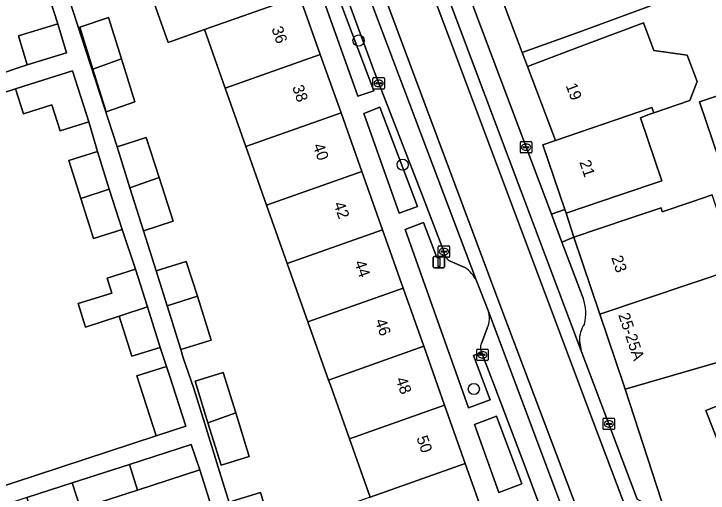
# Model space of a CAD drawing. Extents: x 159371 to 159986, y 382987 to 383597.
# Drawn here: x 159680.8 to 159741.4, y 383240.6 to 383282.5 of the extents above; entities that cross this region are included whole.
import ezdxf

# ---------------------------------------------------------------- set-up
doc = ezdxf.new("R2010")
doc.units = 0
for name, color, linetype in [('IMGEO_Boom', 7, 'Continuous'), ('IMGEO_Erf', 7, 'Continuous'), ('IMGEO_Groenvoorziening', 7, 'Continuous'), ('IMGEO_Kolk', 7, 'Continuous'), ('IMGEO_Lichtmast', 7, 'Continuous'), ('IMGEO_Pand', 7, 'Continuous'), ('IMGEO_Pand_nummerreeks', 7, 'Continuous'), ('IMGEO_Parkeervlak_gesloten', 7, 'Continuous'), ('IMGEO_Parkeervlak_open', 7, 'Continuous'), ('IMGEO_Rijbaan_lokaal_gesloten', 7, 'Continuous'), ('IMGEO_Voetpad_open', 7, 'Continuous')]:
    doc.layers.add(name, color=color, linetype=linetype)

msp = doc.modelspace()

# ---------------------------------------------------------------- linework, layer by layer
at = {"layer": 'IMGEO_Boom'}
for centre in [(159710.901, 383280.138), (159714.755, 383269.277), (159720.969, 383249.658)]:
    msp.add_circle(centre, 0.489, dxfattribs=at)
at = {"layer": 'IMGEO_Erf'}
for points in [[(159682.116, 383294.534), (159689.815, 383270.843), (159692.34, 383271.658), (159693.467, 383268.168), (159694.705, 383264.336), (159692.11, 383263.497), (159693.225, 383260.012), (159695.84, 383260.823), (159696.826, 383257.772), (159698.015, 383253.94), (159695.365, 383253.117), (159695.59, 383252.391), (159696.512, 383249.693), (159697.469, 383246.61), (159698.877, 383242.072), (159702.568, 383230.227)], [(159711.915, 383240.202), (159710.1, 383245.317), (159708.44, 383249.998), (159708.282, 383250.447), (159706.477, 383255.548), (159704.676, 383260.641), (159702.869, 383265.75), (159701.061, 383270.861), (159699.251, 383275.978), (159697.439, 383281.1), (159694.28, 383279.979), (159692.475, 383285.082)], [(159736.412, 383283.168), (159729.903, 383280.793), (159725.198, 383279.1), (159725.656, 383277.87), (159730.333, 383279.64), (159735.782, 383281.701), (159736.698, 383279.28), (159739.618, 383278.871), (159740.492, 383276.551), (159739.844, 383274.897), (159736.695, 383273.822), (159736.17, 383273.643), (159735.541, 383273.369), (159737.394, 383267.859), (159733.76, 383266.636), (159729.021, 383265.042), (159729.705, 383262.938), (159734.445, 383264.533), (159737.321, 383265.5), (159737.433, 383265.168), (159740.025, 383266.04), (159741.795, 383266.635)], [(159678.66, 383240.777), (159693.217, 383245.576), (159691.785, 383250.004), (159691.527, 383250.801), (159694.128, 383251.623), (159693.572, 383253.305), (159691.084, 383252.521), (159689.977, 383256.031), (159687.052, 383255.084), (159686.408, 383257.126), (159689.34, 383258.051), (159688.929, 383259.353), (159691.417, 383260.138), (159690.241, 383263.602), (159687.753, 383262.818), (159686.645, 383266.331), (159685.598, 383269.65), (159688.086, 383270.435), (159687.327, 383273.043), (159684.833, 383272.244), (159684.108, 383274.508), (159681.643, 383273.719), (159680.943, 383275.903), (159668.593, 383271.927)], [(159752.884, 383255.064), (159734.178, 383249.639), (159737.741, 383238.716)]]:
    msp.add_lwpolyline(points, dxfattribs=at)
for points in [[(159684.618, 383281.589), (159682.85, 383287.113), (159677.624, 383285.316), (159676.828, 383287.631), (159671.727, 383285.86), (159666.636, 383284.092), (159665.951, 383283.854), (159661.227, 383282.213), (159663.782, 383274.935), (159667.58, 383276.163), (159668.398, 383273.636), (159664.598, 383272.413), (159664.66, 383272.22), (159668.458, 383273.449), (159678.888, 383276.992), (159681.963, 383278.01), (159681.188, 383280.538)], [(159691.359, 383274.785), (159688.86, 383273.898), (159687.69, 383277.642), (159686.546, 383281.304), (159689.053, 383282.163), (159690.189, 383278.528)], [(159747.16, 383271.296), (159742.405, 383269.697), (159740.696, 383274.778), (159745.451, 383276.377)], [(159752.391, 383243.865), (159748.699, 383242.422), (159744.042, 383240.602), (159741.225, 383247.79), (159744.676, 383249.142), (159744.342, 383250), (159744.129, 383250.542), (159746.505, 383251.472), (159746.938, 383250.368), (159749.457, 383251.355), (159749.987, 383250.002)], [(159700.165, 383247.567), (159701.347, 383243.758), (159698.891, 383242.996), (159697.74, 383246.706), (159696.612, 383250.34), (159699.067, 383251.102)], [(159697.021, 383242.578), (159691.602, 383240.826), (159686.595, 383239.208), (159682.646, 383237.931), (159681.925, 383240.172), (159679.518, 383239.394), (159680.291, 383237.004), (159675.967, 383235.606), (159678.732, 383227.401), (159684.163, 383229.154), (159689.304, 383230.813), (159694.444, 383232.473), (159699.678, 383234.162)], [(159702.32, 383240.621), (159703.388, 383237.179), (159704.594, 383233.291), (159702.139, 383232.53), (159700.963, 383236.318), (159699.864, 383239.859)]]:
    msp.add_lwpolyline(points, close=True, dxfattribs=at)
at = {"layer": 'IMGEO_Groenvoorziening'}
for points in [[(159707.728, 383284.038), (159710.833, 383275.279), (159712.228, 383275.742), (159708.948, 383284.48)], [(159711.367, 383273.769), (159714.458, 383265.05), (159716.04, 383265.621), (159712.77, 383274.324)], [(159725.176, 383241.356), (159722.96, 383247.286), (159721.014, 383246.55), (159723.145, 383240.619)]]:
    msp.add_lwpolyline(points, close=True, dxfattribs=at)
for points in [[(159718.422, 383261.381), (159717.741, 383261.15), (159716.579, 383264.22), (159714.968, 383263.61), (159720.495, 383248.015), (159722.408, 383248.714), (159720.95, 383252.583), (159721.659, 383252.847), (159721.65, 383252.876)], [(159720.195, 383260.284), (159718.897, 383260.852)], [(159722.22, 383256.527), (159721.206, 383259.133)], [(159721.641, 383253.652), (159722.145, 383254.988)]]:
    msp.add_lwpolyline(points, dxfattribs=at)
for centre, radius, start, end in [((159719.275, 383261.669), 0.9, 198.65802, 245.18462), ((159718.608, 383257.871), 2.888, 25.91438, 56.67561), ((159720.191, 383255.855), 2.138, 336.08656, 18.33347), ((159722.306, 383253.272), 0.766, 150.24243, 211.08653)]:
    msp.add_arc(centre, radius, start, end, dxfattribs=at)
at = {"layer": 'IMGEO_Kolk'}
for p, q in [((159712.151, 383275.975), (159712.151, 383276.827)), ((159712.226, 383276.901), (159713.078, 383276.901)), ((159712.639, 383276.681), (159712.664, 383276.681)), ((159713.152, 383276.827), (159713.152, 383275.975)), ((159712.41, 383276.395), (159712.41, 383276.407)), ((159712.848, 383276.358), (159712.45, 383276.358)), ((159712.453, 383276.444), (159712.851, 383276.444)), ((159712.662, 383276.121), (159712.637, 383276.121)), ((159712.894, 383276.407), (159712.894, 383276.395)), ((159713.078, 383275.901), (159712.226, 383275.901)), ((159725.033, 383270.383), (159725.033, 383271.235)), ((159725.108, 383271.309), (159725.96, 383271.309)), ((159726.034, 383271.235), (159726.034, 383270.383)), ((159725.292, 383270.803), (159725.292, 383270.815)), ((159725.73, 383270.766), (159725.332, 383270.766)), ((159725.335, 383270.852), (159725.733, 383270.852)), ((159725.521, 383271.089), (159725.546, 383271.089)), ((159725.776, 383270.815), (159725.776, 383270.803)), ((159725.96, 383270.309), (159725.108, 383270.309)), ((159725.544, 383270.529), (159725.519, 383270.529)), ((159717.93, 383262.184), (159718.782, 383262.184)), ((159717.855, 383261.258), (159717.855, 383262.11)), ((159718.114, 383261.678), (159718.114, 383261.69)), ((159718.552, 383261.641), (159718.154, 383261.641)), ((159718.157, 383261.727), (159718.555, 383261.727)), ((159718.343, 383261.964), (159718.368, 383261.964)), ((159718.598, 383261.69), (159718.598, 383261.678)), ((159718.856, 383262.11), (159718.856, 383261.258)), ((159718.782, 383261.184), (159717.93, 383261.184)), ((159718.366, 383261.404), (159718.341, 383261.404)), ((159721.219, 383252.226), (159721.219, 383253.078)), ((159721.294, 383253.152), (159722.146, 383253.152)), ((159722.22, 383253.078), (159722.22, 383252.226)), ((159721.478, 383252.646), (159721.478, 383252.658)), ((159721.916, 383252.609), (159721.518, 383252.609)), ((159721.521, 383252.695), (159721.919, 383252.695)), ((159721.707, 383252.932), (159721.732, 383252.932)), ((159721.962, 383252.658), (159721.962, 383252.646)), ((159722.146, 383252.152), (159721.294, 383252.152)), ((159721.73, 383252.372), (159721.705, 383252.372)), ((159732.259, 383246.187), (159732.259, 383247.039)), ((159732.334, 383247.113), (159733.186, 383247.113)), ((159733.26, 383247.039), (159733.26, 383246.187)), ((159732.518, 383246.607), (159732.518, 383246.619)), ((159732.956, 383246.57), (159732.558, 383246.57)), ((159732.561, 383246.656), (159732.959, 383246.656)), ((159732.747, 383246.893), (159732.772, 383246.893)), ((159733.002, 383246.619), (159733.002, 383246.607)), ((159733.186, 383246.113), (159732.334, 383246.113)), ((159732.77, 383246.333), (159732.745, 383246.333))]:
    msp.add_line(p, q, dxfattribs=at)
for points in [[(159712.151, 383275.975), (159712.151, 383276.827)], [(159712.226, 383276.901), (159713.078, 383276.901)], [(159713.152, 383276.827), (159713.152, 383275.975)], [(159713.078, 383275.901), (159712.226, 383275.901)], [(159725.033, 383270.383), (159725.033, 383271.235)], [(159725.108, 383271.309), (159725.96, 383271.309)], [(159726.034, 383271.235), (159726.034, 383270.383)], [(159725.96, 383270.309), (159725.108, 383270.309)], [(159717.93, 383262.184), (159718.782, 383262.184)], [(159717.855, 383261.258), (159717.855, 383262.11)], [(159718.856, 383262.11), (159718.856, 383261.258)], [(159718.782, 383261.184), (159717.93, 383261.184)], [(159721.219, 383252.226), (159721.219, 383253.078)], [(159721.294, 383253.152), (159722.146, 383253.152)], [(159722.22, 383253.078), (159722.22, 383252.226)], [(159722.146, 383252.152), (159721.294, 383252.152)], [(159732.259, 383246.187), (159732.259, 383247.039)], [(159732.334, 383247.113), (159733.186, 383247.113)], [(159733.26, 383247.039), (159733.26, 383246.187)], [(159733.186, 383246.113), (159732.334, 383246.113)]]:
    msp.add_lwpolyline(points, dxfattribs=at)
for centre, radius, start, end in [((159712.228, 383276.825), 0.0765, 91.55205, 178.44795), ((159712.228, 383276.825), 0.0765, 91.55205, 178.44795), ((159713.076, 383276.825), 0.0765, 1.55205, 88.44795), ((159713.076, 383276.825), 0.0765, 1.55205, 88.44795), ((159712.45, 383276.404), 0.0403, 85.87752, 175.75265), ((159712.447, 383276.394), 0.0366, 178.93798, 274.71019), ((159712.851, 383276.401), 0.043, 264.86636, 352.45326), ((159712.855, 383276.406), 0.0386, 1.73085, 96.63898), ((159712.228, 383275.977), 0.0765, 181.55205, 268.44795), ((159712.228, 383275.977), 0.0765, 181.55205, 268.44795), ((159713.076, 383275.977), 0.0765, 271.55205, 358.44795), ((159713.076, 383275.977), 0.0765, 271.55205, 358.44795), ((159725.11, 383271.233), 0.0765, 91.55205, 178.44795), ((159725.11, 383271.233), 0.0765, 91.55205, 178.44795), ((159725.958, 383271.233), 0.0765, 1.55205, 88.44795), ((159725.958, 383271.233), 0.0765, 1.55205, 88.44795), ((159725.332, 383270.812), 0.0403, 85.87752, 175.75265), ((159725.329, 383270.802), 0.0366, 178.93798, 274.71019), ((159725.733, 383270.809), 0.043, 264.86636, 352.45326), ((159725.737, 383270.814), 0.0386, 1.73085, 96.63898), ((159725.11, 383270.385), 0.0765, 181.55205, 268.44795), ((159725.11, 383270.385), 0.0765, 181.55205, 268.44795), ((159725.958, 383270.385), 0.0765, 271.55205, 358.44795), ((159725.958, 383270.385), 0.0765, 271.55205, 358.44795), ((159717.932, 383262.108), 0.0765, 91.55205, 178.44795), ((159717.932, 383262.108), 0.0765, 91.55205, 178.44795), ((159718.78, 383262.108), 0.0765, 1.55205, 88.44795), ((159718.78, 383262.108), 0.0765, 1.55205, 88.44795), ((159718.154, 383261.687), 0.0403, 85.87752, 175.75265), ((159718.151, 383261.677), 0.0366, 178.93798, 274.71019), ((159718.555, 383261.684), 0.043, 264.86636, 352.45326), ((159718.559, 383261.689), 0.0386, 1.73085, 96.63898), ((159717.932, 383261.26), 0.0765, 181.55205, 268.44795), ((159717.932, 383261.26), 0.0765, 181.55205, 268.44795), ((159718.78, 383261.26), 0.0765, 271.55205, 358.44795), ((159718.78, 383261.26), 0.0765, 271.55205, 358.44795), ((159721.296, 383253.076), 0.0765, 91.55205, 178.44795), ((159721.296, 383253.076), 0.0765, 91.55205, 178.44795), ((159722.144, 383253.076), 0.0765, 1.55205, 88.44795), ((159722.144, 383253.076), 0.0765, 1.55205, 88.44795), ((159721.518, 383252.655), 0.0403, 85.87752, 175.75265), ((159721.515, 383252.645), 0.0366, 178.93798, 274.71019), ((159721.919, 383252.652), 0.043, 264.86636, 352.45326), ((159721.923, 383252.657), 0.0386, 1.73085, 96.63898), ((159721.296, 383252.228), 0.0765, 181.55205, 268.44795), ((159721.296, 383252.228), 0.0765, 181.55205, 268.44795), ((159722.144, 383252.228), 0.0765, 271.55205, 358.44795), ((159722.144, 383252.228), 0.0765, 271.55205, 358.44795), ((159732.336, 383247.037), 0.0765, 91.55205, 178.44795), ((159732.336, 383247.037), 0.0765, 91.55205, 178.44795), ((159733.184, 383247.037), 0.0765, 1.55205, 88.44795), ((159733.184, 383247.037), 0.0765, 1.55205, 88.44795), ((159732.558, 383246.616), 0.0403, 85.87752, 175.75265), ((159732.555, 383246.606), 0.0366, 178.93798, 274.71019), ((159732.959, 383246.613), 0.043, 264.86636, 352.45326), ((159732.963, 383246.618), 0.0386, 1.73085, 96.63898), ((159732.336, 383246.189), 0.0765, 181.55205, 268.44795), ((159732.336, 383246.189), 0.0765, 181.55205, 268.44795), ((159733.184, 383246.189), 0.0765, 271.55205, 358.44795), ((159733.184, 383246.189), 0.0765, 271.55205, 358.44795)]:
    msp.add_arc(centre, radius, start, end, dxfattribs=at)
for centre, major_axis, ratio, start_param, end_param in [((159712.638, 383276.401), (-0.387, 0.002), 0.722429, 4.712389, 7.853982), ((159712.663, 383276.401), (-0.39, 0.002), 0.717154, 1.570796, 4.712389), ((159725.52, 383270.809), (-0.387, 0.002), 0.722429, 4.712389, 7.853982), ((159725.545, 383270.809), (-0.39, 0.002), 0.717154, 1.570796, 4.712389), ((159718.342, 383261.684), (-0.387, 0.002), 0.722429, 4.712389, 7.853982), ((159718.367, 383261.684), (-0.39, 0.002), 0.717154, 1.570796, 4.712389), ((159721.706, 383252.652), (-0.387, 0.002), 0.722429, 4.712389, 7.853982), ((159721.731, 383252.652), (-0.39, 0.002), 0.717154, 1.570796, 4.712389), ((159732.746, 383246.613), (-0.387, 0.002), 0.722429, 4.712389, 7.853982), ((159732.771, 383246.613), (-0.39, 0.002), 0.717154, 1.570796, 4.712389)]:
    msp.add_ellipse(centre, major_axis=major_axis, ratio=ratio, start_param=start_param, end_param=end_param, dxfattribs=at)
at = {"layer": 'IMGEO_Lichtmast'}
for p, q in [((159717.421, 383260.358), (159717.421, 383261.158)), ((159717.421, 383261.158), (159717.421, 383260.358)), ((159717.521, 383261.258), (159718.311, 383261.258)), ((159718.311, 383261.258), (159717.521, 383261.258)), ((159718.411, 383261.158), (159718.411, 383260.358)), ((159718.411, 383260.358), (159718.411, 383261.158)), ((159718.311, 383260.258), (159717.521, 383260.258)), ((159717.521, 383260.258), (159718.311, 383260.258))]:
    msp.add_line(p, q, dxfattribs=at)
msp.add_lwpolyline([(159717.841, 383261.133), (159717.991, 383261.133), (159717.991, 383260.383), (159717.841, 383260.383), (159717.841, 383261.133)], dxfattribs=at)
for centre, start, end in [((159717.521, 383261.158), 90, 180), ((159717.521, 383261.158), 90, 180), ((159718.311, 383261.158), 0, 90), ((159718.311, 383261.158), 360, 90), ((159717.521, 383260.358), 180, 270), ((159717.521, 383260.358), 180, 270), ((159718.311, 383260.358), 270, 0), ((159718.311, 383260.358), 270, 0)]:
    msp.add_arc(centre, 0.1, start, end, dxfattribs=at)
at = {"layer": 'IMGEO_Pand'}
for points in [[(159726.861, 383290.254), (159726.579, 383290.147), (159726.403, 383290.612), (159721.539, 383288.77), (159725.198, 383279.1), (159729.903, 383280.793), (159736.412, 383283.168), (159735.129, 383286.561), (159735.023, 383286.84), (159729.013, 383284.566)], [(159703.94, 383289.147), (159695.634, 383286.202), (159692.475, 383285.082), (159694.28, 383279.979), (159697.439, 383281.1), (159705.744, 383284.046)], [(159707.559, 383278.917), (159705.744, 383284.046), (159697.439, 383281.1), (159699.251, 383275.978)], [(159687.69, 383277.642), (159690.189, 383278.528), (159689.053, 383282.163), (159686.546, 383281.304)], [(159681.963, 383278.01), (159685.392, 383279.061), (159684.618, 383281.589), (159681.188, 383280.538)], [(159736.695, 383273.822), (159739.844, 383274.897), (159740.492, 383276.551), (159739.618, 383278.871), (159736.698, 383279.28), (159735.782, 383281.701), (159730.333, 383279.64), (159725.656, 383277.87), (159728.11, 383271.385), (159736.528, 383274.271)], [(159690.189, 383278.528), (159687.69, 383277.642), (159688.86, 383273.898), (159691.359, 383274.785)], [(159701.061, 383270.861), (159709.366, 383273.807), (159707.559, 383278.917), (159699.251, 383275.978)], [(159685.902, 383277.492), (159683.408, 383276.693), (159680.943, 383275.903), (159681.643, 383273.719), (159684.108, 383274.508), (159684.833, 383272.244), (159687.327, 383273.043)], [(159740.696, 383274.778), (159742.405, 383269.697), (159747.16, 383271.296), (159745.451, 383276.377)], [(159736.695, 383273.822), (159736.528, 383274.271), (159728.11, 383271.385), (159727.011, 383271.016), (159728.911, 383265.369), (159729.021, 383265.042), (159733.76, 383266.636), (159737.394, 383267.859), (159735.541, 383273.369), (159736.17, 383273.643)], [(159701.061, 383270.861), (159702.869, 383265.75), (159711.174, 383268.697), (159709.366, 383273.807)], [(159689.815, 383270.843), (159690.932, 383267.268), (159693.467, 383268.168), (159692.34, 383271.658)], [(159686.645, 383266.331), (159689.126, 383267.136), (159688.086, 383270.435), (159685.598, 383269.65)], [(159711.174, 383268.697), (159702.869, 383265.75), (159704.676, 383260.641), (159712.978, 383263.595)], [(159693.467, 383268.168), (159690.932, 383267.268), (159692.11, 383263.497), (159694.705, 383264.336)], [(159686.645, 383266.331), (159687.753, 383262.818), (159690.241, 383263.602), (159689.126, 383267.136)], [(159740.025, 383266.04), (159737.433, 383265.168), (159737.321, 383265.5), (159734.445, 383264.533), (159729.705, 383262.938), (159731.97, 383256.207), (159743.947, 383260.236), (159743.531, 383261.474), (159745.86, 383262.098), (159746.219, 383260.757), (159751.409, 383262.148), (159750.66, 383264.941), (159743.051, 383262.901), (159741.795, 383266.635)], [(159712.978, 383263.595), (159704.676, 383260.641), (159706.477, 383255.548), (159714.782, 383258.494)], [(159693.225, 383260.012), (159694.182, 383256.929), (159696.826, 383257.772), (159695.84, 383260.823)], [(159691.417, 383260.138), (159688.929, 383259.353), (159689.34, 383258.051), (159686.408, 383257.126), (159687.052, 383255.084), (159689.977, 383256.031), (159692.459, 383256.835)], [(159752.156, 383257.787), (159745.418, 383255.786), (159744.875, 383257.477), (159743.947, 383260.236), (159731.97, 383256.207), (159734.059, 383249.995), (159734.178, 383249.639), (159752.884, 383255.064)], [(159708.282, 383250.447), (159716.587, 383253.394), (159714.782, 383258.494), (159706.477, 383255.548)], [(159696.826, 383257.772), (159694.182, 383256.929), (159695.365, 383253.117), (159698.015, 383253.94)], [(159689.977, 383256.031), (159691.084, 383252.521), (159693.572, 383253.305), (159692.459, 383256.835)], [(159708.282, 383250.447), (159708.44, 383249.998), (159710.1, 383245.317), (159718.404, 383248.254), (159717.787, 383250), (159716.587, 383253.394)], [(159694.38, 383250.844), (159694.128, 383251.623), (159691.527, 383250.801), (159691.785, 383250.004), (159693.217, 383245.576), (159695.812, 383246.415)], [(159748.699, 383242.422), (159752.391, 383243.865), (159749.987, 383250.002), (159749.457, 383251.355), (159746.938, 383250.368), (159746.505, 383251.472), (159744.129, 383250.542), (159744.342, 383250), (159744.676, 383249.142), (159741.225, 383247.79), (159744.042, 383240.602)], [(159697.74, 383246.706), (159700.165, 383247.567), (159699.067, 383251.102), (159696.612, 383250.34)], [(159711.915, 383240.202), (159720.212, 383243.144), (159718.404, 383248.254), (159710.1, 383245.317)], [(159700.165, 383247.567), (159697.74, 383246.706), (159698.891, 383242.996), (159701.347, 383243.758)], [(159697.021, 383242.578), (159696.286, 383244.815), (159690.881, 383243.068), (159691.602, 383240.826)], [(159691.602, 383240.826), (159690.881, 383243.068), (159685.873, 383241.448), (159686.595, 383239.208)], [(159721.927, 383238.295), (159720.212, 383243.144), (159711.915, 383240.202), (159708.956, 383239.153), (159710.862, 383233.779), (159713.727, 383235.094), (159713.815, 383234.845), (159715.495, 383235.439), (159715.407, 383235.689), (159722.019, 383238.034)], [(159686.595, 383239.208), (159685.873, 383241.448), (159681.925, 383240.172), (159682.646, 383237.931)], [(159700.963, 383236.318), (159703.388, 383237.179), (159702.32, 383240.621), (159699.864, 383239.859)]]:
    msp.add_lwpolyline(points, close=True, dxfattribs=at)
at = {"layer": 'IMGEO_Parkeervlak_gesloten'}
for points in [[(159721.206, 383259.133), (159704.228, 383304.153)], [(159703.96, 383302.861), (159703.513, 383301.93), (159703.479, 383301.171), (159703.559, 383300.908), (159705.532, 383295.785), (159712.289, 383277.365), (159716.543, 383266.423), (159718.357, 383261.684), (159718.413, 383261.409), (159718.422, 383261.381)], [(159718.897, 383260.852), (159720.195, 383260.284)]]:
    msp.add_lwpolyline(points, dxfattribs=at)
for centre, radius, start, end in [((159719.275, 383261.669), 0.9, 198.65802, 245.18462), ((159718.608, 383257.871), 2.888, 25.91438, 56.67561)]:
    msp.add_arc(centre, radius, start, end, dxfattribs=at)
at = {"layer": 'IMGEO_Parkeervlak_open'}
for points in [[(159710.368, 383306.187), (159730.348, 383252.993), (159730.19, 383253.862)], [(159730.515, 383257.594), (159728.665, 383262.501), (159727.743, 383264.944), (159725.675, 383270.428), (159715.145, 383298.483), (159713.007, 383304.098), (159712.914, 383304.285)], [(159733.753, 383225.718), (159722.22, 383256.527)], [(159722.145, 383254.988), (159721.641, 383253.652)], [(159721.65, 383252.876), (159721.659, 383252.847), (159721.72, 383252.652), (159722.734, 383250), (159725.373, 383243.094), (159730.93, 383228.152)]]:
    msp.add_lwpolyline(points, dxfattribs=at)
for centre, radius, start, end in [((159726.79, 383256.266), 3.955, 346.53579, 19.62349), ((159720.191, 383255.855), 2.138, 336.08656, 18.33347), ((159732.747, 383253.902), 2.557, 145.63367, 180.88988), ((159722.306, 383253.272), 0.766, 150.24243, 211.08653)]:
    msp.add_arc(centre, radius, start, end, dxfattribs=at)
at = {"layer": 'IMGEO_Rijbaan_lokaal_gesloten'}
for points in [[(159735.251, 383240.012), (159731.479, 383250), (159730.348, 383252.993), (159710.368, 383306.187), (159709.181, 383305.793), (159710.779, 383301.727), (159718.83, 383280.315), (159731.432, 383246.746), (159741.434, 383220.181)], [(159741.434, 383220.181), (159731.432, 383246.746), (159718.83, 383280.315), (159710.779, 383301.727), (159709.181, 383305.793)], [(159703.728, 383305.614), (159704.036, 383305.065), (159704.228, 383304.153), (159705.436, 383304.551), (159713.205, 383283.99), (159723.406, 383256.576), (159734.857, 383226.26)], [(159723.406, 383256.576), (159713.205, 383283.99), (159705.436, 383304.551), (159704.228, 383304.153), (159721.206, 383259.133), (159722.22, 383256.527), (159733.753, 383225.718), (159734.872, 383222.742), (159735.927, 383219.938), (159736.83, 383217.537), (159751.527, 383178.911), (159752.001, 383177.576)], [(159760.27, 383152.813), (159761.692, 383153.309), (159756.491, 383167.459), (159756.285, 383168.079), (159756.086, 383168.744), (159755.886, 383169.472), (159755.67, 383170.327), (159755.202, 383172.274), (159754.831, 383173.7), (159754.417, 383175.141), (159753.971, 383176.559), (159753.48, 383178.004), (159751.397, 383183.638), (159746.908, 383194.293), (159734.857, 383226.26), (159723.406, 383256.576)]]:
    msp.add_lwpolyline(points, dxfattribs=at)
at = {"layer": 'IMGEO_Voetpad_open'}
for points in [[(159698.031, 383308.107), (159697.322, 383307.856), (159698.504, 383304.515), (159700.334, 383299.34), (159702.135, 383294.249), (159703.94, 383289.147), (159705.744, 383284.046), (159707.559, 383278.917), (159709.366, 383273.807), (159711.174, 383268.697), (159712.978, 383263.595), (159714.782, 383258.494), (159716.587, 383253.394), (159717.787, 383250), (159718.404, 383248.254), (159720.212, 383243.144), (159721.927, 383238.295)], [(159712.914, 383304.285), (159713.007, 383304.098), (159715.145, 383298.483), (159725.675, 383270.428), (159727.743, 383264.944), (159728.911, 383265.369), (159727.011, 383271.016), (159728.11, 383271.385), (159725.656, 383277.87), (159725.198, 383279.1), (159721.539, 383288.77), (159716.588, 383301.853)], [(159725.373, 383243.094), (159722.734, 383250), (159721.72, 383252.652), (159721.659, 383252.847), (159720.95, 383252.583), (159722.408, 383248.714), (159720.495, 383248.015), (159714.968, 383263.61), (159716.579, 383264.22), (159717.741, 383261.15), (159718.422, 383261.381), (159718.413, 383261.409), (159718.357, 383261.684), (159716.543, 383266.423), (159712.289, 383277.365), (159705.532, 383295.785), (159703.559, 383300.908), (159703.479, 383301.171), (159703.513, 383301.93), (159703.96, 383302.861)], [(159702.568, 383230.227), (159698.877, 383242.072), (159697.469, 383246.61), (159696.512, 383249.693), (159695.59, 383252.391), (159695.365, 383253.117), (159694.182, 383256.929), (159693.225, 383260.012), (159692.11, 383263.497), (159690.932, 383267.268), (159689.815, 383270.843), (159682.116, 383294.534), (159680.924, 383298.349), (159679.15, 383297.765), (159680.79, 383293.042), (159682.041, 383289.441), (159682.85, 383287.113), (159684.618, 383281.589), (159685.392, 383279.061), (159681.963, 383278.01), (159678.888, 383276.992)], [(159668.593, 383271.927), (159680.943, 383275.903), (159683.408, 383276.693), (159685.902, 383277.492), (159687.327, 383273.043), (159688.086, 383270.435), (159689.126, 383267.136), (159690.241, 383263.602), (159691.417, 383260.138), (159692.459, 383256.835), (159693.572, 383253.305), (159694.128, 383251.623), (159694.38, 383250.844), (159695.812, 383246.415), (159693.217, 383245.576), (159678.66, 383240.777)], [(159730.19, 383253.862), (159730.348, 383252.993), (159731.479, 383250), (159735.251, 383240.012), (159737.741, 383238.716), (159734.178, 383249.639), (159734.059, 383249.995), (159731.97, 383256.207), (159729.705, 383262.938), (159728.665, 383262.501), (159730.515, 383257.594)], [(159681.925, 383240.172), (159685.873, 383241.448), (159690.881, 383243.068), (159696.286, 383244.815), (159697.021, 383242.578), (159699.678, 383234.162)], [(159730.93, 383228.152), (159725.373, 383243.094)]]:
    msp.add_lwpolyline(points, dxfattribs=at)
for points in [[(159710.833, 383275.279), (159707.728, 383284.038), (159708.948, 383284.48), (159712.228, 383275.742)], [(159714.458, 383265.05), (159711.367, 383273.769), (159712.77, 383274.324), (159716.04, 383265.621)], [(159729.705, 383262.938), (159729.021, 383265.042), (159728.911, 383265.369), (159727.743, 383264.944), (159728.665, 383262.501)], [(159723.145, 383240.619), (159721.014, 383246.55), (159722.96, 383247.286), (159725.176, 383241.356)]]:
    msp.add_lwpolyline(points, close=True, dxfattribs=at)
for centre, radius, start, end in [((159726.79, 383256.266), 3.955, 346.53579, 19.62349), ((159732.747, 383253.902), 2.557, 145.63367, 180.88988)]:
    msp.add_arc(centre, radius, start, end, dxfattribs=at)

# ---------------------------------------------------------------- texts
at = {"layer": 'IMGEO_Pand_nummerreeks'}
for s, rotation, p in [('36', 289.47958, (159703.276, 383281.186)), ('38', 289.47958, (159705.086, 383276.069)), ('19', 290.72723, (159728.98, 383276.207)), ('40', 289.47958, (159706.895, 383270.954)), ('21', 288.59592, (159730.177, 383269.509)), ('42', 289.48035, (159708.703, 383265.846)), ('23', 288.598, (159732.962, 383261.159)), ('44', 289.48035, (159710.513, 383260.729)), ('25-25A', 288.58654, (159733.574, 383256.142)), ('46', 289.47958, (159712.321, 383255.615)), ('48', 289.4686, (159714.129, 383250.508)), ('50', 289.47958, (159715.94, 383245.383))]:
    msp.add_text(s, height=1, rotation=rotation, dxfattribs=at).set_placement(p)

doc.saveas('drawing.dxf')
